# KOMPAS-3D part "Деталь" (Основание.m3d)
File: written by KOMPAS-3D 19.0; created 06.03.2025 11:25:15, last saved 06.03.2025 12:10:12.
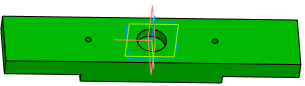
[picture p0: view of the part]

Document properties: Автор: user-2; Полное имя файла: D:\ОПР Врацкий\_Работы 2025\3D\Основание.m3d

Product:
- Part/product: Деталь
    Масса: 3.44027
  - Body: Тело 1
      Масса: 3.44502

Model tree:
1. Эскиз:1
2. Элемент выдавливания:1
     Расстояние 2 = 20
3. Эскиз:2  (with: Элемент выдавливания:1)
4. Элемент выдавливания:2
     Расстояние 1 = 10
5. Эскиз:3  (with: Элемент выдавливания:1)
6. Элемент выдавливания:4
     Расстояние 2 = 11
7. Эскиз:5  (with: Элемент выдавливания:1)
8. Элемент выдавливания:5
     Расстояние 2 = 10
